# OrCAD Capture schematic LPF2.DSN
size A
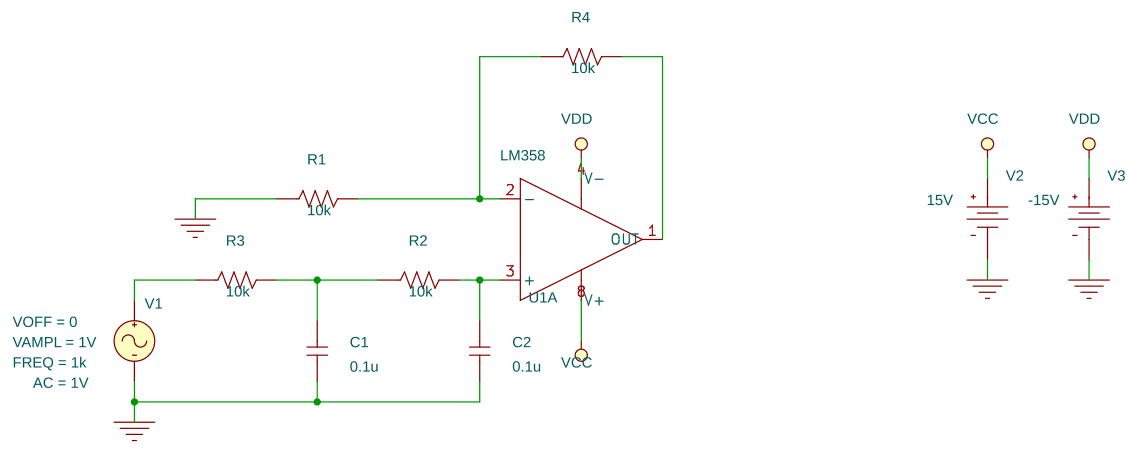
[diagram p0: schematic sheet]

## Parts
C1  0.1u  [cap196]
C2  0.1u  [cap196]
R1  10k  [AXRC05]
R2  10k  [AXRC05]
R3  10k  [AXRC05]
R4  10k  [AXRC05]
U1  LM358  [DIP1008W300L450]  (section A)
V1  VSIN
V2  VDC
V3  VDC

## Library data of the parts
C1 C2 = C
R1-R4 = R
U1 = LM358
V1 = VSIN: AC: 1V; FREQ: 1k; VAMPL: 1V; VOFF: 0
V2 = VDC: DC: 15V
V3 = VDC: DC: -15V

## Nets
VCC: U1.8(V+) V2.0(+)
VDD: U1.4(V-) V3.0(+)
0: C1.1 C2.1 R1.1 V1.2(-) V2.1(-) V3.1(-)
N00197: R1.2 R4.1 U1.2(-)
N00357: R4.2 U1.1(OUT)
N00542: C2.2 R2.2 U1.3(+)
N00550: C1.2 R2.1 R3.2
N00614: R3.1 V1.1(+)
